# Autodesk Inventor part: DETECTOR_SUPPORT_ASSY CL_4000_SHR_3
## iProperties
Shininess: 64.0
Length Units: 11272
Angle Units: 11279
Time Units: 11290
Mass Units: 11286
Length Display Precision: 3
Angle Display Precision: 2
Compacted: True
Part Number: DETECTOR_SUPPORT_ASSY CL_4000_SHR_3
Document SubType Name: Modeling
Created: 2004-08
Designer: John Blackburn
Material: MILD_STEEL
Manufacturer: Standard
Standards Organization: Custom
Density: 0.0
Volumn: 0.0
Area: 0.0
PropertySet Name: Model Information
Control State: 0
Master: False
Checked Out: False
Author: John Blackburn
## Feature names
1. RevolutionAngle1
2. RevolutionAngle2
3. ExtrusionBlind1
4. ExtrusionBlind2
5. ExtrusionMidplane1
6. ExtrusionBlind3
7. ExtrusionBlind4
8. ExtrusionMidplane2
9. RevolutionAngle3
10. ExtrusionMidplane3
11. ExtrusionMidplane4
12. ExtrusionMidplane5
